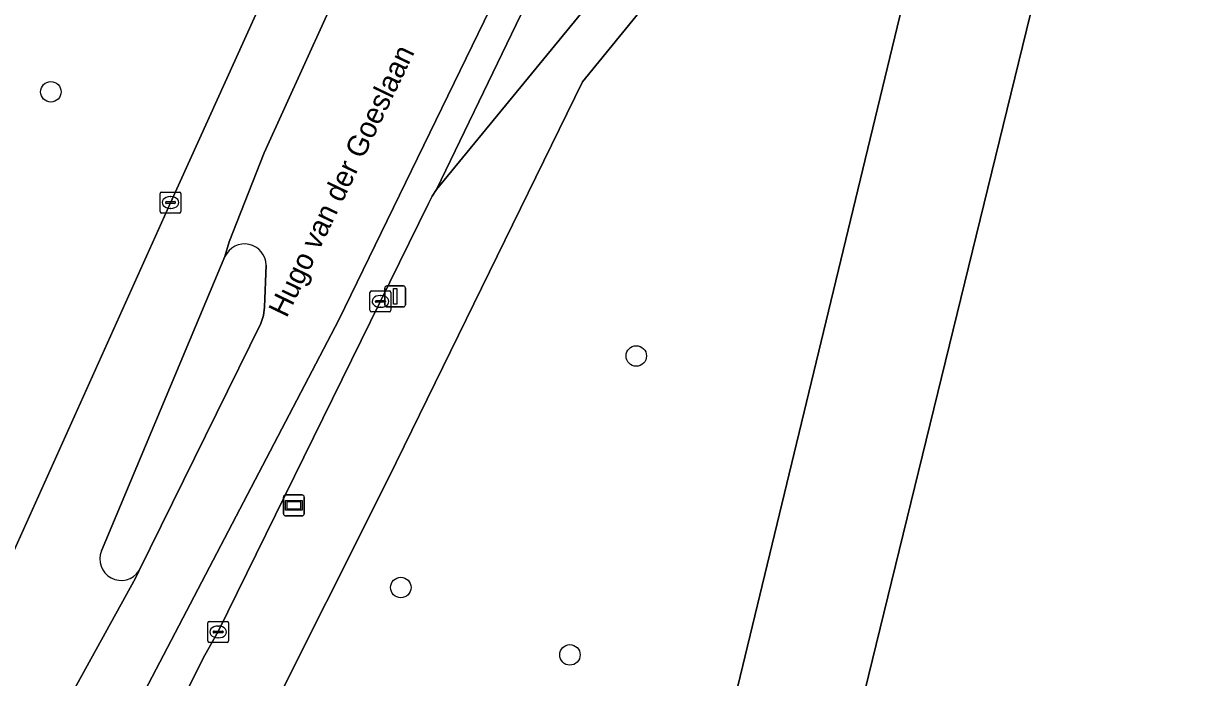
# Model space of a CAD drawing. Extents: x 163043 to 165076, y 382019 to 382874.
# Drawn here: x 163093.6 to 163149.1, y 382604 to 382635.2 of the extents above; entities that cross this region are included whole.
import ezdxf

# ---------------------------------------------------------------- set-up
doc = ezdxf.new("R2010")
doc.units = 0
for name, color, linetype in [('IMGEO_Berm_groen', 7, 'Continuous'), ('IMGEO_Boom', 7, 'Continuous'), ('IMGEO_Erf', 7, 'Continuous'), ('IMGEO_Fietspad_open', 7, 'Continuous'), ('IMGEO_Groenvoorziening', 7, 'Continuous'), ('IMGEO_Hek', 7, 'Continuous'), ('IMGEO_Kolk', 7, 'Continuous'), ('IMGEO_Lichtmast', 7, 'Continuous'), ('IMGEO_Openbare_ruimte_label', 7, 'Continuous'), ('IMGEO_Rijbaan_lokaal_open', 7, 'Continuous'), ('IMGEO_Verkeerseiland_open', 7, 'Continuous'), ('IMGEO_Voetpad_open', 7, 'Continuous'), ('IMGEO_Wegwijzer', 7, 'Continuous')]:
    doc.layers.add(name, color=color, linetype=linetype)

msp = doc.modelspace()

# ---------------------------------------------------------------- linework, layer by layer
at = {"layer": 'IMGEO_Berm_groen'}
for points in [[(163100.668, 382626.691), (163109.118, 382645.334), (163112.554, 382652.908), (163109.419, 382692.051), (163108.904, 382692.167), (163094.101, 382695.441), (163093.938, 382694.712)], [(163145.767, 382678.148), (163151.202, 382677.804), (163151.256, 382678.032), (163150.799, 382678.151), (163144.015, 382679.915), (163140.434, 382677.252), (163135.61, 382663.659), (163134.269, 382660.747), (163135.515, 382660.153), (163131.747, 382652.636), (163129.465, 382647.96), (163128.293, 382645.559), (163124.156, 382637.139), (163120.335, 382632.45), (163111.066, 382613.548), (163105.142, 382601.724), (163104.494, 382600.409), (163102.259, 382595.828), (163102.217, 382595.741), (163104.529, 382594.439), (163105.157, 382594.086), (163115.335, 382588.988)], [(163122.219, 382578.14), (163125.008, 382583.218), (163123.067, 382584.289), (163123.069, 382584.306), (163123.531, 382586.203), (163145.767, 382678.148)], [(163090.891, 382605.042), (163093.076, 382609.823), (163100.668, 382626.691)]]:
    msp.add_lwpolyline(points, dxfattribs=at)
at = {"layer": 'IMGEO_Boom'}
for centre in [(163094.96, 382631.981), (163122.898, 382619.379), (163111.661, 382608.334), (163119.732, 382605.121)]:
    msp.add_circle(centre, 0.489, dxfattribs=at)
at = {"layer": 'IMGEO_Erf'}
msp.add_lwpolyline([(163257.079, 382646.929), (163256.823, 382646.991), (163251.275, 382648.334), (163192.832, 382662.484), (163192.406, 382662.587), (163155.705, 382671.472), (163149.986, 382672.857), (163145.369, 382650.659), (163131.6, 382594.38), (163136.619, 382593.153), (163133.378, 382579.938)], dxfattribs=at)
at = {"layer": 'IMGEO_Fietspad_open'}
msp.add_lwpolyline([(163094.208, 382588.647), (163100.836, 382602.174), (163102.302, 382605.116), (163102.951, 382606.232), (163110.679, 382621.963), (163112.976, 382626.657), (163113.165, 382627.004), (163113.362, 382627.324), (163119.861, 382640.767), (163127.309, 382655.965), (163131.181, 382663.924), (163135.234, 382672.337), (163133.821, 382672.922), (163124.332, 382653.2), (163108.703, 382621.111), (163090.329, 382586.006), (163092.391, 382584.969)], close=True, dxfattribs=at)
at = {"layer": 'IMGEO_Groenvoorziening'}
for points in [[(163149.986, 382672.857), (163151.202, 382677.804), (163145.767, 382678.148), (163123.531, 382586.203), (163123.069, 382584.306), (163123.067, 382584.289), (163125.008, 382583.218), (163132.105, 382579.304)], [(163133.378, 382579.938), (163136.619, 382593.153), (163131.6, 382594.38), (163145.369, 382650.659), (163149.986, 382672.857)]]:
    msp.add_lwpolyline(points, dxfattribs=at)
at = {"layer": 'IMGEO_Hek'}
msp.add_lwpolyline([(163151.202, 382677.804), (163145.767, 382678.148), (163123.531, 382586.203)], dxfattribs=at)
at = {"layer": 'IMGEO_Kolk'}
for p, q in [((163100.169, 382626.273), (163100.169, 382627.125)), ((163100.244, 382627.199), (163101.096, 382627.199)), ((163100.657, 382626.979), (163100.682, 382626.979)), ((163101.17, 382627.125), (163101.17, 382626.273)), ((163100.428, 382626.693), (163100.428, 382626.705)), ((163100.866, 382626.656), (163100.468, 382626.656)), ((163100.471, 382626.742), (163100.869, 382626.742)), ((163100.68, 382626.419), (163100.655, 382626.419)), ((163100.912, 382626.705), (163100.912, 382626.693)), ((163101.096, 382626.199), (163100.244, 382626.199)), ((163110.189, 382621.557), (163110.189, 382622.409)), ((163110.264, 382622.483), (163111.116, 382622.483)), ((163110.448, 382621.977), (163110.448, 382621.989)), ((163110.491, 382622.026), (163110.889, 382622.026)), ((163110.677, 382622.263), (163110.702, 382622.263)), ((163110.932, 382621.989), (163110.932, 382621.977)), ((163111.19, 382622.409), (163111.19, 382621.557)), ((163111.116, 382621.483), (163110.264, 382621.483)), ((163110.886, 382621.94), (163110.488, 382621.94)), ((163110.7, 382621.703), (163110.675, 382621.703)), ((163102.444, 382605.791), (163102.444, 382606.643)), ((163102.519, 382606.717), (163103.371, 382606.717)), ((163102.932, 382606.497), (163102.957, 382606.497)), ((163103.445, 382606.643), (163103.445, 382605.791)), ((163102.703, 382606.211), (163102.703, 382606.223)), ((163103.141, 382606.174), (163102.743, 382606.174)), ((163102.746, 382606.26), (163103.144, 382606.26)), ((163102.955, 382605.937), (163102.93, 382605.937)), ((163103.187, 382606.223), (163103.187, 382606.211)), ((163103.371, 382605.717), (163102.519, 382605.717))]:
    msp.add_line(p, q, dxfattribs=at)
for points in [[(163100.169, 382626.273), (163100.169, 382627.125)], [(163100.244, 382627.199), (163101.096, 382627.199)], [(163101.17, 382627.125), (163101.17, 382626.273)], [(163101.096, 382626.199), (163100.244, 382626.199)], [(163110.189, 382621.557), (163110.189, 382622.409)], [(163110.264, 382622.483), (163111.116, 382622.483)], [(163111.19, 382622.409), (163111.19, 382621.557)], [(163111.116, 382621.483), (163110.264, 382621.483)], [(163102.444, 382605.791), (163102.444, 382606.643)], [(163102.519, 382606.717), (163103.371, 382606.717)], [(163103.445, 382606.643), (163103.445, 382605.791)], [(163103.371, 382605.717), (163102.519, 382605.717)]]:
    msp.add_lwpolyline(points, dxfattribs=at)
for centre, radius, start, end in [((163100.246, 382627.123), 0.0765, 91.552, 178.448), ((163100.246, 382627.123), 0.0765, 91.552, 178.448), ((163101.094, 382627.123), 0.0765, 1.552, 88.448), ((163101.094, 382627.123), 0.0765, 1.552, 88.448), ((163100.468, 382626.702), 0.0403, 85.8775, 175.7526), ((163100.465, 382626.692), 0.0366, 178.938, 274.7102), ((163100.869, 382626.699), 0.043, 264.8664, 352.4533), ((163100.873, 382626.704), 0.0386, 1.7309, 96.639), ((163100.246, 382626.275), 0.0765, 181.552, 268.448), ((163100.246, 382626.275), 0.0765, 181.552, 268.448), ((163101.094, 382626.275), 0.0765, 271.552, 358.448), ((163101.094, 382626.275), 0.0765, 271.552, 358.448), ((163110.266, 382622.407), 0.0765, 91.552, 178.448), ((163110.266, 382622.407), 0.0765, 91.552, 178.448), ((163110.488, 382621.986), 0.0403, 85.8775, 175.7526), ((163110.893, 382621.988), 0.0386, 1.7309, 96.639), ((163111.114, 382622.407), 0.0765, 1.552, 88.448), ((163111.114, 382622.407), 0.0765, 1.552, 88.448), ((163110.266, 382621.559), 0.0765, 181.552, 268.448), ((163110.266, 382621.559), 0.0765, 181.552, 268.448), ((163110.485, 382621.976), 0.0366, 178.938, 274.7102), ((163110.889, 382621.983), 0.043, 264.8664, 352.4533), ((163111.114, 382621.559), 0.0765, 271.552, 358.448), ((163111.114, 382621.559), 0.0765, 271.552, 358.448), ((163102.521, 382606.641), 0.0765, 91.552, 178.448), ((163102.521, 382606.641), 0.0765, 91.552, 178.448), ((163103.369, 382606.641), 0.0765, 1.552, 88.448), ((163103.369, 382606.641), 0.0765, 1.552, 88.448), ((163102.743, 382606.22), 0.0403, 85.8775, 175.7526), ((163102.74, 382606.21), 0.0366, 178.938, 274.7102), ((163103.144, 382606.217), 0.043, 264.8664, 352.4533), ((163103.148, 382606.222), 0.0386, 1.7309, 96.639), ((163102.521, 382605.793), 0.0765, 181.552, 268.448), ((163102.521, 382605.793), 0.0765, 181.552, 268.448), ((163103.369, 382605.793), 0.0765, 271.552, 358.448), ((163103.369, 382605.793), 0.0765, 271.552, 358.448)]:
    msp.add_arc(centre, radius, start, end, dxfattribs=at)
for centre, major_axis, ratio, start_param, end_param in [((163100.656, 382626.699), (-0.387, 0.002), 0.722429, 4.712389, 7.853982), ((163100.681, 382626.699), (-0.39, 0.002), 0.717154, 1.570796, 4.712389), ((163110.676, 382621.983), (-0.387, 0.002), 0.722429, 4.712389, 7.853982), ((163110.701, 382621.983), (-0.39, 0.002), 0.717154, 1.570796, 4.712389), ((163102.931, 382606.217), (-0.387, 0.002), 0.722429, 4.712389, 7.853982), ((163102.956, 382606.217), (-0.39, 0.002), 0.717154, 1.570796, 4.712389)]:
    msp.add_ellipse(centre, major_axis=major_axis, ratio=ratio, start_param=start_param, end_param=end_param, dxfattribs=at)
at = {"layer": 'IMGEO_Lichtmast'}
for p, q in [((163110.894, 382621.819), (163110.894, 382622.619)), ((163110.894, 382622.619), (163110.894, 382621.819)), ((163110.994, 382622.719), (163111.784, 382622.719)), ((163111.784, 382622.719), (163110.994, 382622.719)), ((163111.884, 382622.619), (163111.884, 382621.819)), ((163111.884, 382621.819), (163111.884, 382622.619)), ((163111.784, 382621.719), (163110.994, 382621.719)), ((163110.994, 382621.719), (163111.784, 382621.719))]:
    msp.add_line(p, q, dxfattribs=at)
msp.add_lwpolyline([(163111.314, 382622.594), (163111.464, 382622.594), (163111.464, 382621.844), (163111.314, 382621.844), (163111.314, 382622.594)], dxfattribs=at)
for centre, start, end in [((163110.994, 382622.619), 90, 180), ((163110.994, 382622.619), 90, 180), ((163111.784, 382622.619), 0, 90), ((163111.784, 382622.619), 360, 90), ((163110.994, 382621.819), 180, 270), ((163110.994, 382621.819), 180, 270), ((163111.784, 382621.819), 270, 0), ((163111.784, 382621.819), 270, 0)]:
    msp.add_arc(centre, 0.1, start, end, dxfattribs=at)
at = {"layer": 'IMGEO_Rijbaan_lokaal_open'}
for points in [[(163097.375, 382610.087), (163103.27, 382624.12), (163103.468, 382624.82), (163105.136, 382629.064), (163126.486, 382675.957)], [(163124.332, 382653.2), (163133.821, 382672.922), (163126.486, 382675.957), (163105.136, 382629.064), (163103.468, 382624.82), (163103.27, 382624.12)], [(163121, 382671.566), (163116.347, 382661.27), (163112.554, 382652.908), (163109.118, 382645.334), (163100.668, 382626.691), (163093.076, 382609.823), (163090.891, 382605.042)], [(163131.181, 382663.924), (163127.309, 382655.965), (163119.861, 382640.767), (163113.362, 382627.324), (163122.661, 382638.644), (163122.797, 382638.833), (163122.926, 382639.053), (163126.548, 382646.52), (163130.377, 382654.32), (163130.567, 382655.064), (163130.841, 382662.65)], [(163105.234, 382623.709), (163105.152, 382621.702), (163105.112, 382621.316), (163104.983, 382620.922), (163099.17, 382609.144), (163098.994, 382608.778), (163091.471, 382595.168), (163091.395, 382595.056), (163080.888, 382576.25), (163078.286, 382571.691), (163071.529, 382560.291), (163071.521, 382560.278), (163071.394, 382560.063), (163073.608, 382558.885), (163075.39, 382557.937), (163075.414, 382557.986), (163082.917, 382573.134), (163090.329, 382586.006), (163108.703, 382621.111), (163124.332, 382653.2)], [(163091.395, 382595.056), (163091.471, 382595.168), (163098.994, 382608.778), (163099.17, 382609.144)]]:
    msp.add_lwpolyline(points, dxfattribs=at)
for centre, radius, start, end in [((163104.207, 382623.698), 1.027, 0.587, 155.774), ((163098.312, 382609.691), 1.017, 157.0649, 327.5049)]:
    msp.add_arc(centre, radius, start, end, dxfattribs=at)
at = {"layer": 'IMGEO_Verkeerseiland_open'}
for points in [[(163103.27, 382624.12), (163097.375, 382610.087)], [(163104.983, 382620.922), (163105.112, 382621.316), (163105.152, 382621.702), (163105.234, 382623.709)], [(163099.17, 382609.144), (163104.983, 382620.922)]]:
    msp.add_lwpolyline(points, dxfattribs=at)
for centre, radius, start, end in [((163104.207, 382623.698), 1.027, 0.587, 155.774), ((163098.312, 382609.691), 1.017, 157.0649, 327.5049)]:
    msp.add_arc(centre, radius, start, end, dxfattribs=at)
at = {"layer": 'IMGEO_Voetpad_open'}
msp.add_lwpolyline([(163122.661, 382638.644), (163113.362, 382627.324), (163113.165, 382627.004), (163112.976, 382626.657), (163110.679, 382621.963), (163102.951, 382606.232), (163102.302, 382605.116), (163100.836, 382602.174), (163104.494, 382600.409), (163105.142, 382601.724), (163111.066, 382613.548), (163120.335, 382632.45), (163124.156, 382637.139)], dxfattribs=at)
at = {"layer": 'IMGEO_Wegwijzer'}
for p, q in [((163106.061, 382611.851), (163106.061, 382612.651)), ((163106.061, 382612.651), (163106.061, 382611.851)), ((163106.161, 382612.751), (163106.951, 382612.751)), ((163106.951, 382612.751), (163106.161, 382612.751)), ((163107.051, 382612.651), (163107.051, 382611.851)), ((163107.051, 382611.851), (163107.051, 382612.651)), ((163106.951, 382611.751), (163106.161, 382611.751)), ((163106.161, 382611.751), (163106.951, 382611.751))]:
    msp.add_line(p, q, dxfattribs=at)
for points in [[(163106.162, 382612.483), (163106.95, 382612.483), (163106.95, 382612.019), (163106.162, 382612.019), (163106.162, 382612.483)], [(163106.227, 382612.418), (163106.227, 382612.084), (163106.885, 382612.084), (163106.885, 382612.418), (163106.227, 382612.418)]]:
    msp.add_lwpolyline(points, dxfattribs=at)
for centre, start, end in [((163106.161, 382612.651), 90, 180), ((163106.161, 382612.651), 90, 180), ((163106.951, 382612.651), 0, 90), ((163106.951, 382612.651), 360, 90), ((163106.161, 382611.851), 180, 270), ((163106.161, 382611.851), 180, 270), ((163106.951, 382611.851), 270, 0), ((163106.951, 382611.851), 270, 0)]:
    msp.add_arc(centre, 0.1, start, end, dxfattribs=at)

# ---------------------------------------------------------------- texts
at = {"layer": 'IMGEO_Openbare_ruimte_label'}
msp.add_text('Hugo van der Goeslaan', height=1, rotation=64.2805, dxfattribs=at).set_placement((163106.208, 382621.162))

doc.saveas('drawing.dxf')
